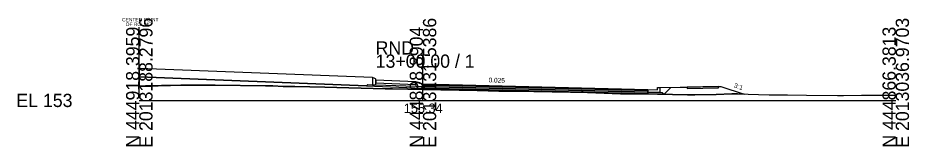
# Model space of a CAD drawing. Extents: x -26 to 163, y -10 to 7518.
# Drawn here: x -25.7 to 162.8, y 5990.3 to 6017.5 of the extents above; entities that cross this region are included whole.
import ezdxf

# ---------------------------------------------------------------- set-up
doc = ezdxf.new("R2010")
doc.units = 0
for name, color, linetype in [('Exist Cross Section Cell', 7, 'Continuous'), ('Exist XS Center Line Elevation Label', 7, 'Continuous'), ('Exist XS Ground Line', 7, 'Continuous'), ('Prop CMT Conc Surface', 7, 'Continuous'), ('Prop CMT Concrete Structures', 7, 'Continuous'), ('Prop CMT Pvmt Course 1', 7, 'Continuous'), ('Prop CMT Pvmt Course 1 CG', 7, 'Continuous'), ('Prop CMT Pvmt Course 2', 7, 'Continuous'), ('Prop CMT Pvmt Course 3', 7, 'Continuous'), ('Prop CMT Pvmt Surface', 7, 'Continuous'), ('Prop CMT Shear Line', 7, 'Continuous'), ('Prop CMT Shear Line Text', 7, 'Continuous'), ('Prop CMT Slope Grass', 7, 'Continuous'), ('Prop CMT Subgrade Earthwork', 7, 'Continuous'), ('Prop XS Earthwork Shape', 7, 'Continuous'), ('Prop XS SE Text', 7, 'Continuous'), ('Prop XS Side Slope Text', 7, 'Continuous')]:
    doc.layers.add(name, color=color, linetype=linetype)

msp = doc.modelspace()

# ---------------------------------------------------------------- linework, layer by layer
at = {"layer": 'Exist Cross Section Cell'}
for p, q in [((60, 6000), (60, 6009.72)), ((0, 6000), (60, 6000)), ((60, 6000), (160, 6000))]:
    msp.add_line(p, q, dxfattribs=at)
at = {"layer": 'Exist XS Ground Line'}
msp.add_lwpolyline([(0, 6003.05), (1.32, 6003.08), (2.53, 6003.1), (3.6, 6003.12), (3.97, 6003.12), (4.71, 6003.14), (6.6, 6003.17), (8.82, 6003.21), (9.48, 6003.23), (10.12, 6003.24), (10.86, 6003.24), (11.64, 6003.24), (12.2, 6003.24), (16.06, 6003.24), (26.69, 6003.12), (28.23, 6003.09), (30.45, 6002.94), (32.93, 6002.94), (39.27, 6002.81), (52.01, 6002.48), (52.5, 6002.47), (52.87, 6002.47), (53.23, 6002.46), (53.58, 6002.46), (60, 6002.34), (71.43, 6002.13), (76.07, 6001.94), (83.42, 6001.86), (91.23, 6001.78), (93.88, 6001.74), (94.79, 6001.7), (101.75, 6001.43), (105.36, 6001.37), (109.62, 6001.29), (115.94, 6001.19), (117.49, 6001.15), (121.99, 6001.27), (125.36, 6001.37), (126.51, 6001.36), (133.23, 6001.2), (137.09, 6001.16), (141.1, 6001.12), (147.67, 6001.06), (148.97, 6001.05), (152.76, 6001.1), (156.84, 6001.14), (158.24, 6001.14), (160, 6001.13)], dxfattribs=at)
at = {"layer": 'Prop CMT Conc Surface'}
for points in [[(50, 6004.5), (49.96, 6004.6), (49.85, 6004.65), (49.34, 6004.83)], [(50, 6004.33), (50, 6004.5)], [(60, 6003.54), (59.25, 6003.56), (59.25, 6003.72), (58.5, 6003.97)], [(115.88, 6002.84), (120.88, 6002.94)], [(107.59, 6002.34), (109.58, 6002.21)], [(109.58, 6002.21), (109.59, 6002.71), (110.08, 6002.71)]]:
    msp.add_lwpolyline(points, dxfattribs=at)
at = {"layer": 'Prop CMT Concrete Structures'}
for points in [[(50, 6004.5), (49.96, 6004.6), (49.85, 6004.65), (49.34, 6004.83)], [(49.34, 6004.83), (49.34, 6003.33)], [(49.34, 6003.33), (50, 6003.33)], [(50, 6004.33), (50, 6004.5)], [(50, 6003.33), (50, 6004.33)], [(50, 6004.33), (50, 6003.75)], [(58.5, 6003.97), (50, 6004.32)], [(50, 6003.73), (58.5, 6003.39)], [(60, 6003.54), (59.25, 6003.56), (59.25, 6003.72), (58.5, 6003.97)], [(58.5, 6003.97), (58.5, 6002.99)], [(58.5, 6003.39), (58.5, 6003.97)], [(58.5, 6002.99), (60, 6002.96)], [(60, 6002.96), (60, 6003.54)], [(122.5, 6002.97), (115.88, 6002.84)], [(122.5, 6002.64), (122.5, 6002.97)], [(107.59, 6002.34), (109.58, 6002.21), (109.59, 6002.71), (110.08, 6002.71)], [(110.08, 6002.71), (110.08, 6001.7), (107.59, 6001.76)], [(107.59, 6001.76), (107.59, 6002.34)], [(115.88, 6002.84), (115.88, 6002.51)], [(115.88, 6002.51), (122.5, 6002.64)]]:
    msp.add_lwpolyline(points, dxfattribs=at)
at = {"layer": 'Prop CMT Pvmt Course 1'}
for points in [[(60, 6003.54), (107.59, 6002.34)], [(60, 6003.29), (60, 6003.54)], [(107.59, 6002.09), (60, 6003.29)], [(107.59, 6002.34), (107.59, 6002.09)]]:
    msp.add_lwpolyline(points, dxfattribs=at)
msp.add_lwpolyline([(60, 6003.29), (60, 6003.41), (60, 6003.41), (60, 6003.29)], close=True, dxfattribs=at)
at = {"layer": 'Prop CMT Pvmt Course 1 CG'}
for points in [[(60, 6002.62), (60, 6002.96)], [(107.59, 6001.76), (110.58, 6001.69), (110.92, 6001.34)], [(107.59, 6001.43), (107.59, 6001.76)], [(111.01, 6001.34), (107.59, 6001.43)]]:
    msp.add_lwpolyline(points, dxfattribs=at)
at = {"layer": 'Prop CMT Pvmt Course 2'}
for points in [[(60, 6002.96), (60, 6003.29)], [(60, 6003.29), (107.59, 6002.09)], [(107.59, 6001.76), (60, 6002.96)], [(107.59, 6002.09), (107.59, 6001.76)]]:
    msp.add_lwpolyline(points, dxfattribs=at)
at = {"layer": 'Prop CMT Pvmt Course 3'}
for points in [[(50, 6003.33), (58.5, 6002.99)], [(60, 6002.96), (107.59, 6001.76)], [(60, 6002.62), (60, 6002.96)], [(107.59, 6001.43), (60, 6002.62)], [(107.59, 6001.76), (107.59, 6001.43)]]:
    msp.add_lwpolyline(points, dxfattribs=at)
at = {"layer": 'Prop CMT Pvmt Surface'}
msp.add_lwpolyline([(60, 6003.54), (107.59, 6002.34)], dxfattribs=at)
at = {"layer": 'Prop CMT Shear Line'}
msp.add_line((0, 6000.48), (0, 6015.48), dxfattribs=at)
at = {"layer": 'Prop CMT Slope Grass'}
for p, q in [((49.34, 6004.82), (0, 6006.79)), ((48.06, 6003.1), (0, 6005.02))]:
    msp.add_line(p, q, dxfattribs=at)
msp.add_lwpolyline([(110.08, 6002.71), (123, 6002.97), (127.96, 6001.32)], dxfattribs=at)
at = {"layer": 'Prop CMT Subgrade Earthwork'}
for p, q in [((0, 6006.79), (0, 6003.05)), ((48.34, 6003.37), (48.06, 6003.1))]:
    msp.add_line(p, q, dxfattribs=at)
for points in [[(48.06, 6003.1), (60, 6002.62)], [(48.34, 6003.37), (49.34, 6003.33)], [(60, 6002.62), (107.59, 6001.43)], [(107.59, 6001.43), (111.01, 6001.34), (112.42, 6002.76)]]:
    msp.add_lwpolyline(points, dxfattribs=at)
at = {"layer": 'Prop XS Earthwork Shape'}
msp.add_lwpolyline([(112.43, 6002.77), (115.88, 6002.84), (115.88, 6002.51), (122.5, 6002.64), (122.5, 6002.97), (123, 6002.97), (127.96, 6001.32), (126.51, 6001.36), (125.36, 6001.37), (121.99, 6001.27), (117.49, 6001.15), (115.94, 6001.19), (109.62, 6001.29), (105.36, 6001.37), (101.75, 6001.43), (94.79, 6001.7), (93.88, 6001.74), (91.23, 6001.78), (83.42, 6001.86), (76.07, 6001.94), (71.43, 6002.13), (60, 6002.34), (53.58, 6002.46), (53.23, 6002.46), (52.87, 6002.47), (52.5, 6002.47), (52.01, 6002.48), (39.27, 6002.81), (32.93, 6002.94), (30.45, 6002.94), (28.23, 6003.09), (26.69, 6003.12), (16.06, 6003.24), (12.2, 6003.24), (11.64, 6003.24), (10.86, 6003.24), (10.12, 6003.24), (9.48, 6003.23), (8.82, 6003.21), (6.6, 6003.17), (4.71, 6003.14), (3.97, 6003.12), (3.6, 6003.12), (2.53, 6003.1), (1.32, 6003.08), (0, 6003.05), (0, 6005.02), (48.06, 6003.1), (60, 6002.62), (107.59, 6001.43), (111.01, 6001.34)], close=True, dxfattribs=at)

# ---------------------------------------------------------------- texts
at = {"layer": 'Exist Cross Section Cell'}
for s, p in [('E 2013188.2796', (2.8, 5990)), ('E 2013131.5386', (62.8, 5990)), ('E 2013036.9703', (162.8, 5990)), ('N 444918.3959', (0, 5990)), ('N 444898.8904', (60, 5990)), ('N 444866.3813', (160, 5990))]:
    msp.add_text(s, height=2.8, rotation=90, dxfattribs=at).set_placement(p)
for s, p in [('RND', (50, 6009.72)), ('13+00.00 / 1', (50, 6006.92)), ('EL 153', (-26, 5998.6))]:
    msp.add_text(s, height=2.8, dxfattribs=at).set_placement(p)
at = {"layer": 'Exist XS Center Line Elevation Label'}
msp.add_text('155.34', height=2, dxfattribs=at).set_placement((55.96, 5997.34))
at = {"layer": 'Prop CMT Shear Line Text'}
for s, p in [('CENTER POINT', (-3.64, 6016.73)), ('OF ROUND', (-2.88, 6015.75))]:
    msp.add_text(s, height=0.75, dxfattribs=at).set_placement(p)
at = {"layer": 'Prop XS SE Text'}
msp.add_text('0.025', height=1, rotation=358.5613, dxfattribs=at).set_placement((73.87, 6003.82))
at = {"layer": 'Prop XS Side Slope Text'}
msp.add_text('3:1', height=1, rotation=341.5651, dxfattribs=at).set_placement((125.69, 6002.76))

doc.saveas('drawing.dxf')
